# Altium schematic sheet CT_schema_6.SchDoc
size 277 x 170 mm
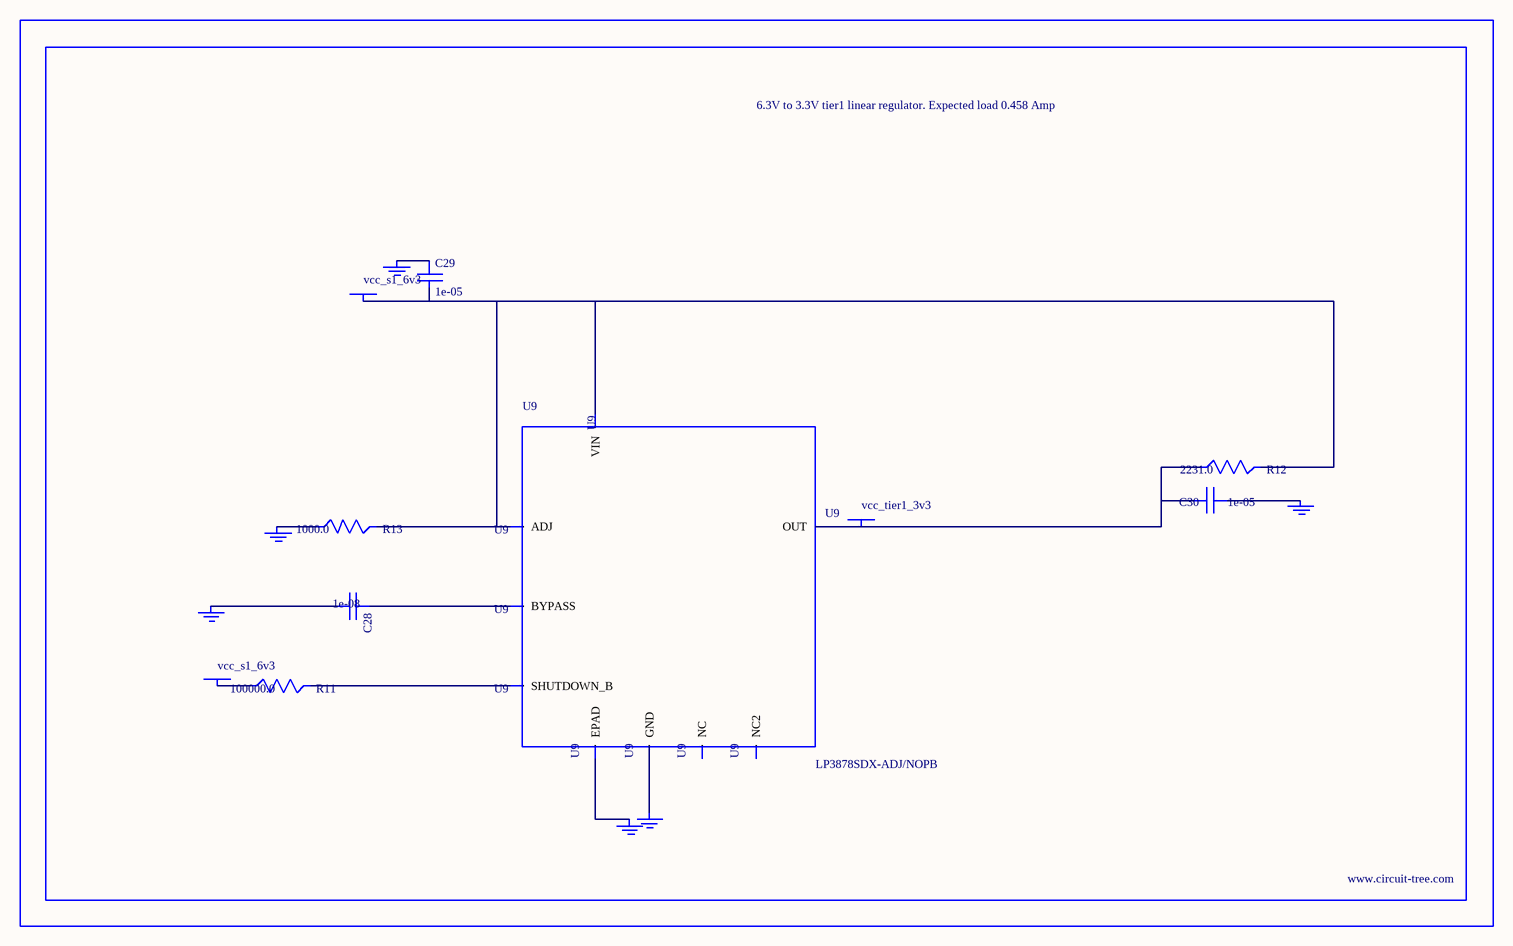
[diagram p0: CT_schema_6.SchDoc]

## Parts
BORDER5  (no value)
C28  1e-08  [C0402]
C29  1e-05  [C1206]
C30  1e-05  [C1210]
GND_INSTANCE_5_0  (no value)
GND_INSTANCE_5_1  (no value)
GND_INSTANCE_5_2  (no value)
GND_INSTANCE_5_3  (no value)
GND_INSTANCE_5_4  (no value)
GND_INSTANCE_5_5  (no value)
POWER_INSTANCE_5_0  vcc_s1_6v3
POWER_INSTANCE_5_1  vcc_s1_6v3
POWER_INSTANCE_5_2  vcc_tier1_3v3
R11  100000.0  [R0603]
R12  2231.0  [R0603]
R13  1000.0  [R0603]
U9  LP3878SDX-ADJ/NOPB  [WSON-8]

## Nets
NetC28_1: C28.1 U9.1(BYPASS)
NetC28_2: C28.2 GND_INSTANCE_5_0.0(GND)
NetC29_1: C29.1 GND_INSTANCE_5_1.0(GND)
NetC29_2: C29.2 POWER_INSTANCE_5_0.0(PWR) R12.2 R13.2 U9.4(VIN) U9.6(ADJ)
NetC30_1: C30.1 GND_INSTANCE_5_2.0(GND)
NetC30_2: C30.2 POWER_INSTANCE_5_2.0(PWR) R12.1 U9.5(OUT)
NetGND_INSTANCE_5_3_0: GND_INSTANCE_5_3.0(GND) R13.1
NetGND_INSTANCE_5_4_0: GND_INSTANCE_5_4.0(GND) U9.PAD(EPAD)
NetGND_INSTANCE_5_5_0: GND_INSTANCE_5_5.0(GND) U9.3(GND)
NetPOWER_INSTANCE_5_1_0: POWER_INSTANCE_5_1.0(PWR) R11.1
NetR11_2: R11.2 U9.8(SHUTDOWN_B)

Not connected (* = marked no-connect by the designer): U9 2(NC) 7(NC2)

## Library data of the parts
BORDER5 = BORDER_PAGE5
C28 = C0402C103K3RAC
C29 = C1206C106K3RACTU
C30 = GRM32DR61E106MA12L
GND_INSTANCE_5_0-GND_INSTANCE_5_5 = GND
POWER_INSTANCE_5_0-POWER_INSTANCE_5_2 = PWR
R11 = RC0603JR-07100KL
R12 = R12
R13 = RC0603JR-071KL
